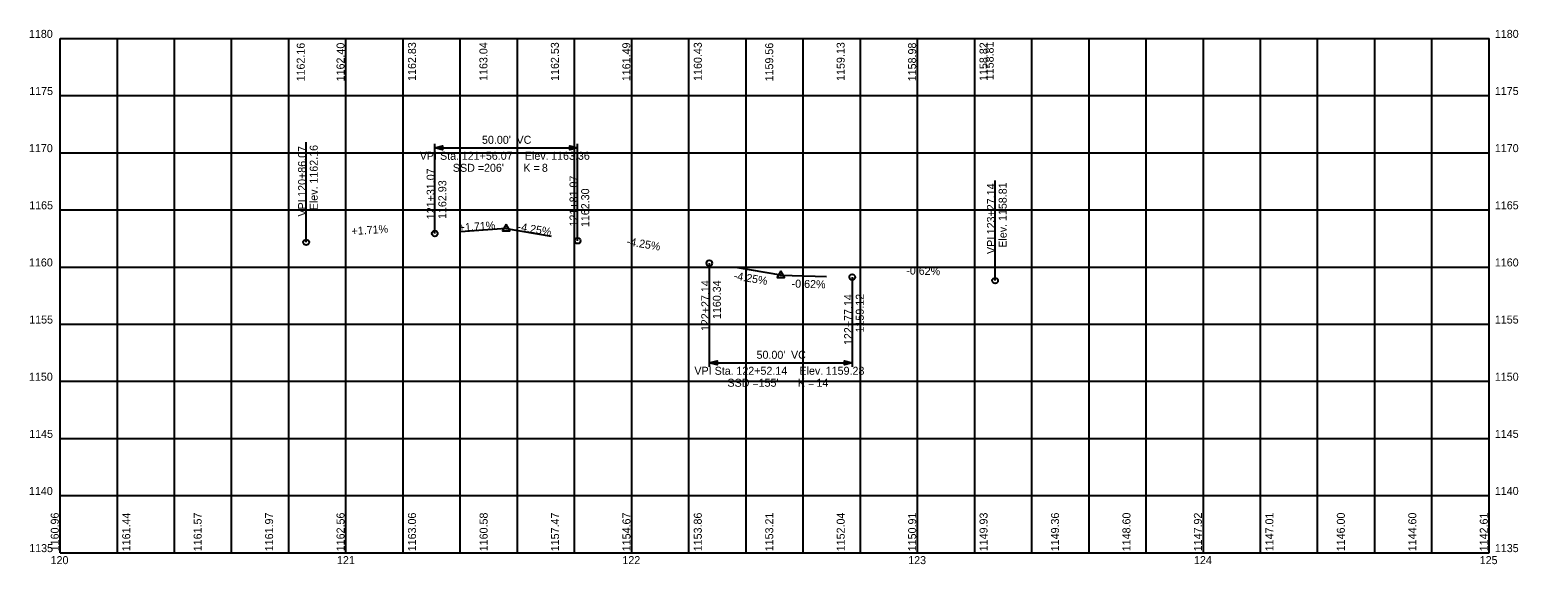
# Model space of a CAD drawing. Extents: x -11 to 510, y 1131 to 1318.
import ezdxf

# ---------------------------------------------------------------- set-up
doc = ezdxf.new("R2010")
doc.units = 0
for name, color, linetype in [('PF_P_Sta_Elev_Text', 7, 'Continuous'), ('PF_P_Text', 7, 'Continuous'), ('PF_P_Text_Curve', 7, 'Continuous'), ('PF_P_Text_Grade', 7, 'Continuous'), ('PF_P_Text_Points', 7, 'Continuous'), ('PF_P_Text_Strip_Grades_20', 7, 'Continuous'), ('PF_X_Text_Strip_Grade', 7, 'Continuous'), ('SH_Major_Grid_Line', 7, 'Continuous')]:
    doc.layers.add(name, color=color, linetype=linetype)

msp = doc.modelspace()

# ---------------------------------------------------------------- linework, layer by layer
at = {"layer": 'PF_P_Text'}
for points in [[(156.07, 1249.88), (154.82, 1247.71), (157.32, 1247.71)], [(252.14, 1233.54), (250.89, 1231.38), (253.39, 1231.38)]]:
    msp.add_lwpolyline(points, close=True, dxfattribs=at)
at = {"layer": 'PF_P_Text_Curve'}
for p, q in [((131.07, 1246.72), (131.07, 1278.12)), ((131.07, 1276.82), (131.07, 1276.62)), ((131.07, 1276.72), (181.07, 1276.72)), ((181.07, 1244.18), (181.07, 1278.12)), ((181.07, 1276.62), (181.07, 1276.82)), ((227.14, 1236.35), (227.14, 1200.08)), ((277.14, 1231.48), (277.14, 1200.08)), ((227.14, 1201.58), (227.14, 1201.38)), ((227.14, 1201.48), (277.14, 1201.48)), ((277.14, 1201.38), (277.14, 1201.58))]:
    msp.add_line(p, q, dxfattribs=at)
for points in [[(131.07, 1276.72), (133.79, 1277.4), (133.79, 1276.04)], [(181.07, 1276.72), (178.35, 1276.04), (178.35, 1277.4)], [(227.14, 1201.48), (229.86, 1202.16), (229.86, 1200.8)], [(277.14, 1201.48), (274.42, 1200.8), (274.42, 1202.16)]]:
    msp.add_lwpolyline(points, close=True, dxfattribs=at)
for centre in [(131.07, 1246.72), (181.07, 1244.18), (227.14, 1236.35), (277.14, 1231.48)]:
    msp.add_circle(centre, 1, dxfattribs=at)
at = {"layer": 'PF_P_Text_Grade'}
for p, q in [((156.07, 1248.43), (140.11, 1247.34)), ((156.07, 1248.43), (156.07, 1248.43)), ((156.07, 1248.43), (171.84, 1245.75)), ((252.14, 1232.1), (236.37, 1234.78)), ((252.14, 1232.1), (252.14, 1232.1)), ((252.14, 1232.1), (268.14, 1231.7))]:
    msp.add_line(p, q, dxfattribs=at)
for centre in [(156.07, 1248.43), (156.07, 1248.43), (252.14, 1232.1), (252.14, 1232.1)]:
    msp.add_circle(centre, 0.1, dxfattribs=at)
at = {"layer": 'PF_P_Text_Points'}
for p, q in [((86.07, 1243.64), (86.07, 1278.64)), ((327.14, 1230.23), (327.14, 1265.23))]:
    msp.add_line(p, q, dxfattribs=at)
for centre in [(86.07, 1243.64), (327.14, 1230.23)]:
    msp.add_circle(centre, 1, dxfattribs=at)
at = {"layer": 'SH_Major_Grid_Line'}
for p, q in [((0, 1315), (500, 1315)), ((0, 1135), (0, 1315)), ((0, 1135), (0, 1315)), ((20, 1135), (20, 1315)), ((40, 1135), (40, 1315)), ((60, 1135), (60, 1315)), ((80, 1135), (80, 1315)), ((100, 1135), (100, 1315)), ((120, 1135), (120, 1315)), ((140, 1135), (140, 1315)), ((160, 1135), (160, 1315)), ((180, 1135), (180, 1315)), ((200, 1135), (200, 1315)), ((220, 1135), (220, 1315)), ((240, 1135), (240, 1315)), ((260, 1135), (260, 1315)), ((280, 1135), (280, 1315)), ((300, 1135), (300, 1315)), ((320, 1135), (320, 1315)), ((340, 1135), (340, 1315)), ((360, 1135), (360, 1315)), ((380, 1135), (380, 1315)), ((400, 1135), (400, 1315)), ((420, 1135), (420, 1315)), ((440, 1135), (440, 1315)), ((460, 1135), (460, 1315)), ((480, 1135), (480, 1315)), ((500, 1135), (500, 1315)), ((500, 1135), (500, 1315)), ((0, 1295), (500, 1295)), ((0, 1275), (500, 1275)), ((0, 1255), (500, 1255)), ((0, 1235), (500, 1235)), ((0, 1215), (500, 1215)), ((0, 1195), (500, 1195)), ((0, 1175), (500, 1175)), ((0, 1155), (500, 1155)), ((0, 1135), (500, 1135))]:
    msp.add_line(p, q, dxfattribs=at)

# ---------------------------------------------------------------- texts
at = {"layer": 'PF_P_Sta_Elev_Text'}
for s, p in [('1180', (-10.93, 1315.2)), ('1180', (502, 1315.2)), ('1175', (-10.84, 1295.2)), ('1175', (502, 1295.2)), ('1170', (-10.93, 1275.2)), ('1170', (502, 1275.2)), ('1165', (-10.84, 1255.2)), ('1165', (502, 1255.2)), ('1160', (-10.93, 1235.2)), ('1160', (502, 1235.2)), ('1155', (-10.84, 1215.2)), ('1155', (502, 1215.2)), ('1150', (-10.93, 1195.2)), ('1150', (502, 1195.2)), ('1145', (-10.84, 1175.2)), ('1145', (502, 1175.2)), ('1140', (-10.93, 1155.2)), ('1140', (502, 1155.2)), ('1135', (-10.84, 1135.2)), ('1135', (502, 1135.2)), ('120', (-3.35, 1131)), ('121', (96.85, 1131)), ('122', (196.72, 1131)), ('123', (296.73, 1131)), ('124', (396.73, 1131)), ('125', (496.7, 1131))]:
    msp.add_text(s, height=2.8, dxfattribs=at).set_placement(p)
at = {"layer": 'PF_P_Text_Curve'}
for s, p in [("50.00'", (147.59, 1278.12)), (' VC', (158.62, 1278.12)), ('VPI Sta. ', (125.83, 1272.52)), ('SSD = ', (137.4, 1268.32)), ('121+56.07', (140.51, 1272.52)), ("206'", (148.3, 1268.32)), ('K = ', (162.07, 1268.32)), ('   Elev. ', (159.47, 1272.52)), ('8', (168.55, 1268.32)), ('1163.36', (171.78, 1272.52)), ("50.00'", (243.66, 1202.88)), (' VC', (254.69, 1202.88)), ('VPI Sta. ', (221.92, 1197.28)), ('122+52.14', (236.6, 1197.28)), ('   Elev. ', (255.56, 1197.28)), ('1159.28', (267.87, 1197.28)), ('SSD = ', (233.47, 1193.08)), ("155'", (244.37, 1193.08)), ('K = ', (258.14, 1193.08)), ('14', (264.62, 1193.08))]:
    msp.add_text(s, height=2.8, dxfattribs=at).set_placement(p)
at = {"layer": 'PF_P_Text_Grade'}
for s, rotation, p in [('+1.71%', 3.9129, (139.56, 1247.38)), ('-4.25%', 350.352, (159.91, 1247.86)), ('+1.71%', 3.9129, (102.04, 1246.14)), ('-4.25%', 350.352, (198.07, 1242.69)), ('-0.62%', 358.5729, (296.02, 1232.41)), ('-4.25%', 350.352, (235.54, 1230.66)), ('-0.62%', 358.5729, (255.91, 1227.81))]:
    msp.add_text(s, height=2.8, rotation=rotation, dxfattribs=at).set_placement(p)
at = {"layer": 'PF_P_Text_Points'}
for s, p in [('120+86.07', (86.03, 1259.56)), ('1162.16', (90.12, 1264.19)), ('121+31.07', (131.03, 1251.72)), ('121+81.07', (181.03, 1249.18)), ('Elev. ', (90.12, 1254.87)), ('1162.93', (135.12, 1251.81)), ('1162.30', (185.1, 1248.97)), ('123+27.14', (327.1, 1246.44)), ('1158.81', (331.19, 1251.08)), ('VPI ', (86.03, 1252.67)), ('VPI ', (327.1, 1239.55)), ('Elev. ', (331.19, 1241.76)), ('122+27.14', (227.12, 1212.56)), ('1160.34', (231.17, 1216.78)), ('122+77.14', (277.12, 1207.68)), ('1159.12', (281.19, 1212.07))]:
    msp.add_text(s, height=2.8, rotation=90, dxfattribs=at).set_placement(p)
at = {"layer": 'PF_P_Text_Strip_Grades_20'}
for s, p in [('1162.16', (85.57, 1299.96)), ('1162.40', (99.5, 1299.99)), ('1162.83', (124.5, 1300.14)), ('1163.04', (149.5, 1300.14)), ('1162.53', (174.5, 1300.14)), ('1161.49', (199.51, 1300.04)), ('1160.43', (224.51, 1300.14)), ('1159.56', (249.5, 1299.96)), ('1159.13', (274.5, 1300.14)), ('1158.98', (299.5, 1300.01)), ('1158.82', (324.5, 1300.12)), ('1158.81', (326.64, 1300.38))]:
    msp.add_text(s, height=2.8, rotation=90, dxfattribs=at).set_placement(p)
at = {"layer": 'PF_X_Text_Strip_Grade'}
for s, p in [('1160.96', (-0.5, 1135.5)), ('1161.44', (24.5, 1135.5)), ('1161.57', (49.5, 1135.5)), ('1161.97', (74.5, 1135.5)), ('1162.56', (99.5, 1135.5)), ('1163.06', (124.5, 1135.5)), ('1160.58', (149.56, 1135.5)), ('1157.47', (174.54, 1135.5)), ('1154.67', (199.54, 1135.5)), ('1153.86', (224.5, 1135.5)), ('1153.21', (249.51, 1135.5)), ('1152.04', (274.51, 1135.5)), ('1150.91', (299.51, 1135.5)), ('1149.93', (324.5, 1135.5)), ('1149.36', (349.5, 1135.5)), ('1148.60', (374.5, 1135.5)), ('1147.92', (399.5, 1135.5)), ('1147.01', (424.51, 1135.5)), ('1146.00', (449.51, 1135.5)), ('1144.60', (474.52, 1135.5)), ('1142.61', (499.53, 1135.5))]:
    msp.add_text(s, height=2.8, rotation=90, dxfattribs=at).set_placement(p)

doc.saveas('drawing.dxf')
